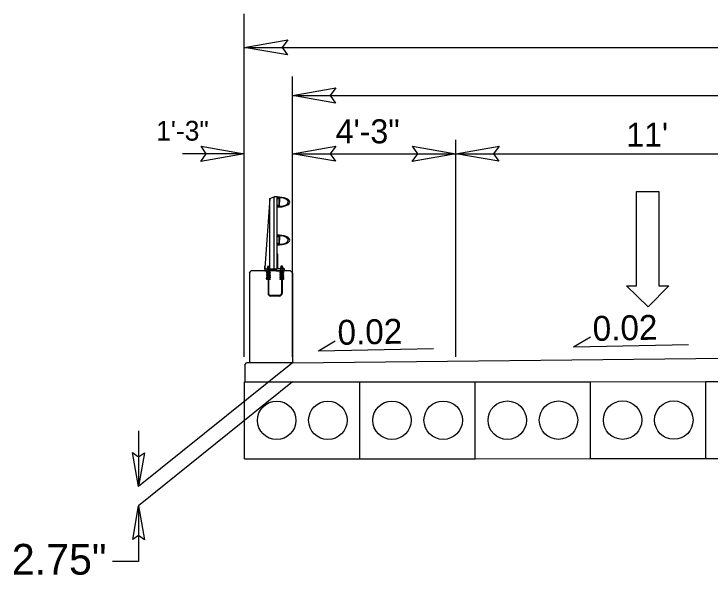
# Model space of a CAD drawing. Extents: x 1733676 to 1734289, y 540979 to 541226.
# Drawn here: x 1734244.27 to 1734262.38, y 541079.57 to 541094.17 of the extents above; entities that cross this region are included whole.
import ezdxf

# ---------------------------------------------------------------- set-up
doc = ezdxf.new("R2010")
doc.units = 0
for name, color, linetype in [('Prop Dimension', 7, 'Continuous'), ('Prop Lane Arrow CELL', 7, 'Continuous'), ('Prop Terminator CELL', 7, 'Continuous'), ('Typical Bridge Rail Two Bar CELL', 7, 'Continuous'), ('Typical Pavement Slope CELL', 7, 'Continuous'), ('Typical Pavement Slope Information CELL', 7, 'Continuous'), ('Typical Slope Point Local CELL', 7, 'Continuous'), ('Typical Terminator CELL', 7, 'Continuous')]:
    doc.layers.add(name, color=color, linetype=linetype)

msp = doc.modelspace()

# ---------------------------------------------------------------- linework, layer by layer
at = {"layer": 'Prop Dimension'}
for p, q in [((1734250.259, 541085.248), (1734250.259, 541094.168)), ((1734250.259, 541093.296), (1734283.259, 541093.296)), ((1734251.509, 541085.248), (1734251.509, 541092.543)), ((1734251.509, 541092.043), (1734282.009, 541092.043)), ((1734255.759, 541085.248), (1734255.759, 541090.891)), ((1734250.259, 541090.531), (1734248.654, 541090.531)), ((1734251.509, 541090.531), (1734255.759, 541090.531)), ((1734255.759, 541090.531), (1734266.759, 541090.531)), ((1734251.51, 541085.092), (1734247.509, 541081.869)), ((1734256.266, 541084.595), (1734259.266, 541084.597)), ((1734259.266, 541084.597), (1734262.266, 541084.599)), ((1734259.267, 541082.597), (1734259.266, 541084.597)), ((1734259.267, 541082.597), (1734259.266, 541084.597)), ((1734262.266, 541084.599), (1734265.266, 541084.601)), ((1734262.267, 541082.599), (1734262.266, 541084.599)), ((1734262.267, 541082.599), (1734262.266, 541084.599)), ((1734251.51, 541084.593), (1734247.509, 541081.369)), ((1734250.266, 541084.592), (1734253.266, 541084.594)), ((1734250.267, 541082.592), (1734250.266, 541084.592)), ((1734253.266, 541084.594), (1734256.266, 541084.595)), ((1734253.267, 541082.594), (1734253.266, 541084.594)), ((1734253.267, 541082.594), (1734253.266, 541084.594)), ((1734256.267, 541082.595), (1734256.266, 541084.595)), ((1734256.267, 541082.595), (1734256.266, 541084.595)), ((1734247.509, 541083.321), (1734247.509, 541081.869)), ((1734250.267, 541082.592), (1734253.267, 541082.594)), ((1734253.267, 541082.594), (1734256.267, 541082.595)), ((1734256.267, 541082.595), (1734259.267, 541082.597)), ((1734259.267, 541082.597), (1734262.267, 541082.599)), ((1734262.267, 541082.599), (1734265.267, 541082.601)), ((1734247.509, 541081.369), (1734247.509, 541079.917)), ((1734247.509, 541079.917), (1734246.832, 541079.917))]:
    msp.add_line(p, q, dxfattribs=at)
for centre in [(1734251.1, 541083.592), (1734252.433, 541083.593), (1734254.1, 541083.594), (1734255.433, 541083.595), (1734257.1, 541083.596), (1734258.433, 541083.597), (1734260.1, 541083.598), (1734261.433, 541083.599)]:
    msp.add_circle(centre, 0.5, dxfattribs=at)
at = {"layer": 'Prop Lane Arrow CELL'}
for p, q in [((1734260.466, 541087.093), (1734260.466, 541089.543)), ((1734260.466, 541089.543), (1734261.043, 541089.543)), ((1734261.043, 541089.543), (1734261.043, 541087.093)), ((1734260.763, 541086.542), (1734260.203, 541087.093)), ((1734260.203, 541087.093), (1734260.466, 541087.093)), ((1734261.306, 541087.093), (1734260.763, 541086.542)), ((1734261.043, 541087.093), (1734261.306, 541087.093))]:
    msp.add_line(p, q, dxfattribs=at)
at = {"layer": 'Prop Terminator CELL'}
for points in [[(1734251.384, 541093.102), (1734250.259, 541093.296), (1734251.39, 541093.496), (1734251.246, 541093.296)], [(1734252.634, 541091.849), (1734251.509, 541092.043), (1734252.64, 541092.243), (1734252.496, 541092.043)], [(1734249.134, 541090.725), (1734250.259, 541090.531), (1734249.128, 541090.331), (1734249.271, 541090.531)], [(1734252.634, 541090.338), (1734251.509, 541090.531), (1734252.64, 541090.731), (1734252.496, 541090.531)], [(1734254.634, 541090.725), (1734255.759, 541090.531), (1734254.628, 541090.331), (1734254.771, 541090.531)], [(1734256.884, 541090.338), (1734255.759, 541090.531), (1734256.89, 541090.731), (1734256.746, 541090.531)]]:
    msp.add_lwpolyline(points, close=True, dxfattribs=at)
at = {"layer": 'Typical Bridge Rail Two Bar CELL'}
for p, q in [((1734250.922, 541089.368), (1734250.791, 541087.56)), ((1734250.922, 541089.368), (1734251.036, 541089.406)), ((1734250.922, 541087.522), (1734250.922, 541089.368)), ((1734251.111, 541089.406), (1734251.036, 541089.406)), ((1734251.036, 541087.522), (1734251.036, 541089.406)), ((1734251.111, 541087.522), (1734251.111, 541089.406)), ((1734251.174, 541089.374), (1734251.174, 541089.272)), ((1734251.174, 541089.17), (1734251.174, 541089.272)), ((1734250.922, 541088.504), (1734250.918, 541088.504)), ((1734251.174, 541088.387), (1734251.174, 541088.285)), ((1734251.174, 541088.183), (1734251.174, 541088.285)), ((1734250.791, 541087.522), (1734250.791, 541087.56)), ((1734250.794, 541087.581), (1734250.794, 541087.614)), ((1734250.863, 541087.439), (1734250.863, 541087.522)), ((1734250.907, 541087.598), (1734250.864, 541087.598)), ((1734250.864, 541087.598), (1734250.864, 541087.563)), ((1734250.907, 541087.563), (1734250.907, 541087.598)), ((1734250.907, 541087.439), (1734250.907, 541087.522)), ((1734251.21, 541087.448), (1734251.21, 541087.532)), ((1734251.256, 541087.608), (1734251.213, 541087.608)), ((1734251.213, 541087.608), (1734251.213, 541087.572)), ((1734251.256, 541087.572), (1734251.256, 541087.608)), ((1734251.258, 541087.448), (1734251.258, 541087.532)), ((1734250.392, 541087.435), (1734250.441, 541087.484)), ((1734250.392, 541087.435), (1734250.392, 541085.091)), ((1734251.461, 541087.484), (1734250.441, 541087.484)), ((1734250.934, 541087.448), (1734250.834, 541087.448)), ((1734250.934, 541087.437), (1734250.834, 541087.437)), ((1734250.876, 541087.404), (1734250.834, 541087.404)), ((1734250.876, 541087.393), (1734250.834, 541087.393)), ((1734250.876, 541087.359), (1734250.834, 541087.359)), ((1734250.876, 541087.348), (1734250.834, 541087.348)), ((1734250.876, 541087.315), (1734250.834, 541087.315)), ((1734250.876, 541087.426), (1734250.856, 541087.426)), ((1734250.876, 541087.415), (1734250.856, 541087.415)), ((1734250.876, 541087.381), (1734250.856, 541087.381)), ((1734250.876, 541087.37), (1734250.856, 541087.37)), ((1734250.876, 541087.337), (1734250.856, 541087.337)), ((1734250.876, 541087.326), (1734250.856, 541087.326)), ((1734250.892, 541087.426), (1734250.876, 541087.426)), ((1734250.876, 541087.426), (1734250.876, 541086.895)), ((1734250.912, 541087.426), (1734250.892, 541087.426)), ((1734250.892, 541087.426), (1734250.892, 541086.895)), ((1734250.912, 541087.415), (1734250.892, 541087.415)), ((1734250.934, 541087.404), (1734250.892, 541087.404)), ((1734250.934, 541087.393), (1734250.892, 541087.393)), ((1734250.912, 541087.381), (1734250.892, 541087.381)), ((1734250.912, 541087.37), (1734250.892, 541087.37)), ((1734250.934, 541087.359), (1734250.892, 541087.359)), ((1734250.934, 541087.348), (1734250.892, 541087.348)), ((1734250.912, 541087.337), (1734250.892, 541087.337)), ((1734250.912, 541087.326), (1734250.892, 541087.326)), ((1734250.934, 541087.315), (1734250.892, 541087.315)), ((1734251.283, 541087.448), (1734251.182, 541087.448)), ((1734251.283, 541087.437), (1734251.182, 541087.437)), ((1734251.224, 541087.404), (1734251.182, 541087.404)), ((1734251.224, 541087.393), (1734251.182, 541087.393)), ((1734251.224, 541087.359), (1734251.182, 541087.359)), ((1734251.224, 541087.348), (1734251.182, 541087.348)), ((1734251.224, 541087.315), (1734251.182, 541087.315)), ((1734251.224, 541087.426), (1734251.205, 541087.426)), ((1734251.224, 541087.415), (1734251.205, 541087.415)), ((1734251.224, 541087.381), (1734251.205, 541087.381)), ((1734251.224, 541087.37), (1734251.205, 541087.37)), ((1734251.224, 541087.337), (1734251.205, 541087.337)), ((1734251.224, 541087.326), (1734251.205, 541087.326)), ((1734251.241, 541087.426), (1734251.224, 541087.426)), ((1734251.224, 541087.426), (1734251.224, 541086.895)), ((1734251.261, 541087.426), (1734251.241, 541087.426)), ((1734251.241, 541087.426), (1734251.241, 541086.895)), ((1734251.261, 541087.415), (1734251.241, 541087.415)), ((1734251.283, 541087.404), (1734251.241, 541087.404)), ((1734251.283, 541087.393), (1734251.241, 541087.393)), ((1734251.261, 541087.381), (1734251.241, 541087.381)), ((1734251.261, 541087.37), (1734251.241, 541087.37)), ((1734251.283, 541087.359), (1734251.241, 541087.359)), ((1734251.283, 541087.348), (1734251.241, 541087.348)), ((1734251.261, 541087.337), (1734251.241, 541087.337)), ((1734251.261, 541087.326), (1734251.241, 541087.326)), ((1734251.283, 541087.315), (1734251.241, 541087.315)), ((1734251.461, 541087.484), (1734251.51, 541087.435)), ((1734251.51, 541087.435), (1734251.51, 541085.091)), ((1734250.876, 541087.304), (1734250.834, 541087.304)), ((1734250.876, 541087.27), (1734250.834, 541087.27)), ((1734250.876, 541087.259), (1734250.834, 541087.259)), ((1734250.876, 541087.292), (1734250.856, 541087.292)), ((1734250.876, 541087.281), (1734250.856, 541087.281)), ((1734250.934, 541087.304), (1734250.892, 541087.304)), ((1734250.912, 541087.292), (1734250.892, 541087.292)), ((1734250.912, 541087.281), (1734250.892, 541087.281)), ((1734250.934, 541087.27), (1734250.892, 541087.27)), ((1734250.934, 541087.259), (1734250.892, 541087.259)), ((1734251.224, 541087.304), (1734251.182, 541087.304)), ((1734251.224, 541087.27), (1734251.182, 541087.27)), ((1734251.224, 541087.259), (1734251.182, 541087.259)), ((1734251.224, 541087.292), (1734251.205, 541087.292)), ((1734251.224, 541087.281), (1734251.205, 541087.281)), ((1734251.283, 541087.304), (1734251.241, 541087.304)), ((1734251.261, 541087.292), (1734251.241, 541087.292)), ((1734251.261, 541087.281), (1734251.241, 541087.281)), ((1734251.283, 541087.27), (1734251.241, 541087.27)), ((1734251.283, 541087.259), (1734251.241, 541087.259)), ((1734251.171, 541086.842), (1734250.946, 541086.842)), ((1734251.171, 541086.825), (1734250.946, 541086.825)), ((1734250.272, 541085.037), (1734250.32, 541085.091)), ((1734250.401, 541085.091), (1734250.32, 541085.091)), ((1734251.51, 541085.091), (1734250.401, 541085.091))]:
    msp.add_line(p, q, dxfattribs=at)
for points in [[(1734251.111, 541089.142), (1734251.111, 541089.19), (1734251.131, 541089.19), (1734251.131, 541089.182), (1734251.13, 541089.182), (1734251.13, 541089.162), (1734251.162, 541089.162), (1734251.166, 541089.193), (1734251.166, 541089.272), (1734251.166, 541089.351), (1734251.162, 541089.382), (1734251.13, 541089.382), (1734251.13, 541089.362), (1734251.131, 541089.362), (1734251.131, 541089.354), (1734251.111, 541089.354), (1734251.111, 541089.403)], [(1734251.111, 541088.154), (1734251.111, 541088.203), (1734251.131, 541088.203), (1734251.131, 541088.195), (1734251.13, 541088.195), (1734251.13, 541088.175), (1734251.162, 541088.175), (1734251.166, 541088.206), (1734251.166, 541088.285), (1734251.166, 541088.364), (1734251.162, 541088.395), (1734251.13, 541088.395), (1734251.13, 541088.375), (1734251.131, 541088.375), (1734251.131, 541088.366), (1734251.111, 541088.366), (1734251.111, 541088.415)], [(1734251.304, 541087.484), (1734251.304, 541087.532), (1734251.13, 541087.532), (1734251.13, 541087.918), (1734251.111, 541087.918), (1734251.111, 541087.522), (1734250.799, 541087.522), (1734250.799, 541087.55), (1734250.791, 541087.55), (1734250.791, 541087.484), (1734250.941, 541087.484), (1734250.941, 541087.51), (1734251.092, 541087.51), (1734251.092, 541087.484), (1734251.304, 541087.484)], [(1734250.928, 541087.521), (1734250.928, 541087.53), (1734250.885, 541087.53), (1734250.842, 541087.53), (1734250.842, 541087.521)], [(1734250.917, 541087.53), (1734250.917, 541087.557), (1734250.912, 541087.563), (1734250.859, 541087.563), (1734250.853, 541087.557), (1734250.853, 541087.53), (1734250.917, 541087.53), (1734250.896, 541087.53), (1734250.896, 541087.557), (1734250.901, 541087.563), (1734250.896, 541087.557), (1734250.891, 541087.563), (1734250.88, 541087.563), (1734250.874, 541087.557), (1734250.874, 541087.53), (1734250.874, 541087.557), (1734250.869, 541087.563)], [(1734251.278, 541087.531), (1734251.278, 541087.54), (1734251.235, 541087.54), (1734251.192, 541087.54), (1734251.192, 541087.531)], [(1734251.266, 541087.539), (1734251.266, 541087.567), (1734251.261, 541087.572), (1734251.208, 541087.572), (1734251.202, 541087.567), (1734251.202, 541087.539), (1734251.266, 541087.539), (1734251.244, 541087.539), (1734251.244, 541087.567), (1734251.25, 541087.572), (1734251.244, 541087.567), (1734251.239, 541087.572), (1734251.228, 541087.572), (1734251.223, 541087.567), (1734251.223, 541087.539), (1734251.223, 541087.567), (1734251.218, 541087.572)], [(1734250.834, 541087.448), (1734250.834, 541087.437), (1734250.856, 541087.426), (1734250.856, 541087.415), (1734250.834, 541087.404), (1734250.834, 541087.393), (1734250.856, 541087.381), (1734250.856, 541087.37), (1734250.834, 541087.359), (1734250.834, 541087.348), (1734250.856, 541087.337), (1734250.856, 541087.326), (1734250.834, 541087.315), (1734250.834, 541087.304), (1734250.856, 541087.292), (1734250.856, 541087.281), (1734250.834, 541087.27), (1734250.834, 541087.259)], [(1734250.934, 541087.448), (1734250.934, 541087.437), (1734250.912, 541087.426), (1734250.912, 541087.415), (1734250.934, 541087.404), (1734250.934, 541087.393), (1734250.912, 541087.381), (1734250.912, 541087.37), (1734250.934, 541087.359), (1734250.934, 541087.348), (1734250.912, 541087.337), (1734250.912, 541087.326), (1734250.934, 541087.315), (1734250.934, 541087.304), (1734250.912, 541087.292), (1734250.912, 541087.281), (1734250.934, 541087.27), (1734250.934, 541087.259)], [(1734251.182, 541087.448), (1734251.182, 541087.437), (1734251.205, 541087.426), (1734251.205, 541087.415), (1734251.182, 541087.404), (1734251.182, 541087.393), (1734251.205, 541087.381), (1734251.205, 541087.37), (1734251.182, 541087.359), (1734251.182, 541087.348), (1734251.205, 541087.337), (1734251.205, 541087.326), (1734251.182, 541087.315), (1734251.182, 541087.304), (1734251.205, 541087.292), (1734251.205, 541087.281), (1734251.182, 541087.27), (1734251.182, 541087.259)], [(1734251.283, 541087.448), (1734251.283, 541087.437), (1734251.261, 541087.426), (1734251.261, 541087.415), (1734251.283, 541087.404), (1734251.283, 541087.393), (1734251.261, 541087.381), (1734251.261, 541087.37), (1734251.283, 541087.359), (1734251.283, 541087.348), (1734251.261, 541087.337), (1734251.261, 541087.326), (1734251.283, 541087.315), (1734251.283, 541087.304), (1734251.261, 541087.292), (1734251.261, 541087.281), (1734251.283, 541087.27), (1734251.283, 541087.259)]]:
    msp.add_lwpolyline(points, dxfattribs=at)
for centre in [(1734250.843, 541087.287), (1734251.274, 541087.287)]:
    msp.add_circle(centre, 0.00834, dxfattribs=at)
for centre, radius, start, end in [((1734251.182, 541089.374), 0.00783, 90, 180), ((1734251.182, 541089.17), 0.00783, 180, 270), ((1734251.182, 541088.387), 0.00783, 90, 180), ((1734251.182, 541088.183), 0.00783, 180, 270), ((1734250.946, 541086.895), 0.07, 180, 270), ((1734250.946, 541086.895), 0.0534, 180, 270), ((1734251.171, 541086.895), 0.0534, 270, 0), ((1734251.171, 541086.895), 0.07, 270, 0)]:
    msp.add_arc(centre, radius, start, end, dxfattribs=at)
for centre, major_axis, ratio, start_param, end_param in [((1734251.111, 541089.272), (0.334, 0), 0.39036, 6.282787, 7.853967), ((1734251.182, 541089.272), (0.222, 0), 0.495501, 6.282718, 7.853881), ((1734251.111, 541089.272), (0.334, 0), 0.39036, 4.712404, 6.282787), ((1734251.182, 541089.272), (0.222, 0), 0.495501, 4.712489, 6.282718), ((1734251.111, 541088.285), (0.334, 0), 0.39036, 6.282787, 7.853967), ((1734251.111, 541088.285), (0.334, 0), 0.39036, 4.712404, 6.282787), ((1734251.182, 541088.285), (0.222, 0), 0.495501, 6.282718, 7.853881), ((1734251.182, 541088.285), (0.222, 0), 0.495501, 4.712489, 6.282718)]:
    msp.add_ellipse(centre, major_axis=major_axis, ratio=ratio, start_param=start_param, end_param=end_param, dxfattribs=at)
at = {"layer": 'Typical Pavement Slope CELL'}
for p, q in [((1734251.51, 541085.092), (1734266.759, 541085.248)), ((1734250.272, 541085.037), (1734250.272, 541084.592))]:
    msp.add_line(p, q, dxfattribs=at)
at = {"layer": 'Typical Pavement Slope Information CELL'}
for p, q in [((1734258.826, 541085.504), (1734259.263, 541085.768)), ((1734252.188, 541085.401), (1734252.626, 541085.665)), ((1734258.826, 541085.504), (1734261.817, 541085.564)), ((1734252.188, 541085.401), (1734255.18, 541085.461))]:
    msp.add_line(p, q, dxfattribs=at)
at = {"layer": 'Typical Terminator CELL'}
for points in [[(1734247.66, 541082.747), (1734247.509, 541081.869), (1734247.353, 541082.752), (1734247.509, 541082.64)], [(1734247.358, 541080.491), (1734247.509, 541081.369), (1734247.665, 541080.486), (1734247.509, 541080.598)]]:
    msp.add_lwpolyline(points, close=True, dxfattribs=at)

# ---------------------------------------------------------------- texts
at = {"layer": 'Typical Pavement Slope Information CELL'}
for p in [(1734252.69, 541085.556), (1734259.328, 541085.659)]:
    msp.add_text('0.02', height=0.6476, rotation=1.1457, dxfattribs=at).set_placement(p)
at = {"layer": 'Typical Slope Point Local CELL'}
for s, height, p in [('1\'-3"', 0.5141, (1734247.966, 541090.871)), ('4\'-3"', 0.6249, (1734252.637, 541090.801)), ("11'", 0.6249, (1734260.195, 541090.712)), ('2.75"', 0.8, (1734244.212, 541079.577))]:
    msp.add_text(s, height=height, rotation=360, dxfattribs=at).set_placement(p)

doc.saveas('drawing.dxf')
